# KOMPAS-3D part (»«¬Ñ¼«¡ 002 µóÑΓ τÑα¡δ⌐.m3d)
File: created 22.07.2016 16:41:15, last saved 22.07.2016 17:02:06.
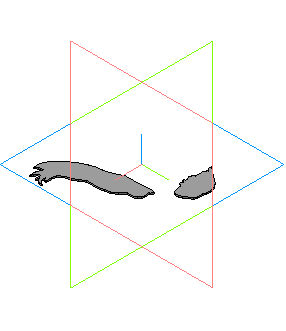
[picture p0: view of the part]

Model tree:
1. Эскиз:1
2. Операция выдавливания:1
     Расстояние 1 = 0.5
